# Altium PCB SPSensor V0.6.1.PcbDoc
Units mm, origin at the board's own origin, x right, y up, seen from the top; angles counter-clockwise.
Board outline 97.48 x 57.45 mm, 2 copper layers (TopLayer, BottomLayer), stack 1.671 mm thick; 106 components, 64 nets, 349 pads, 163 vias.
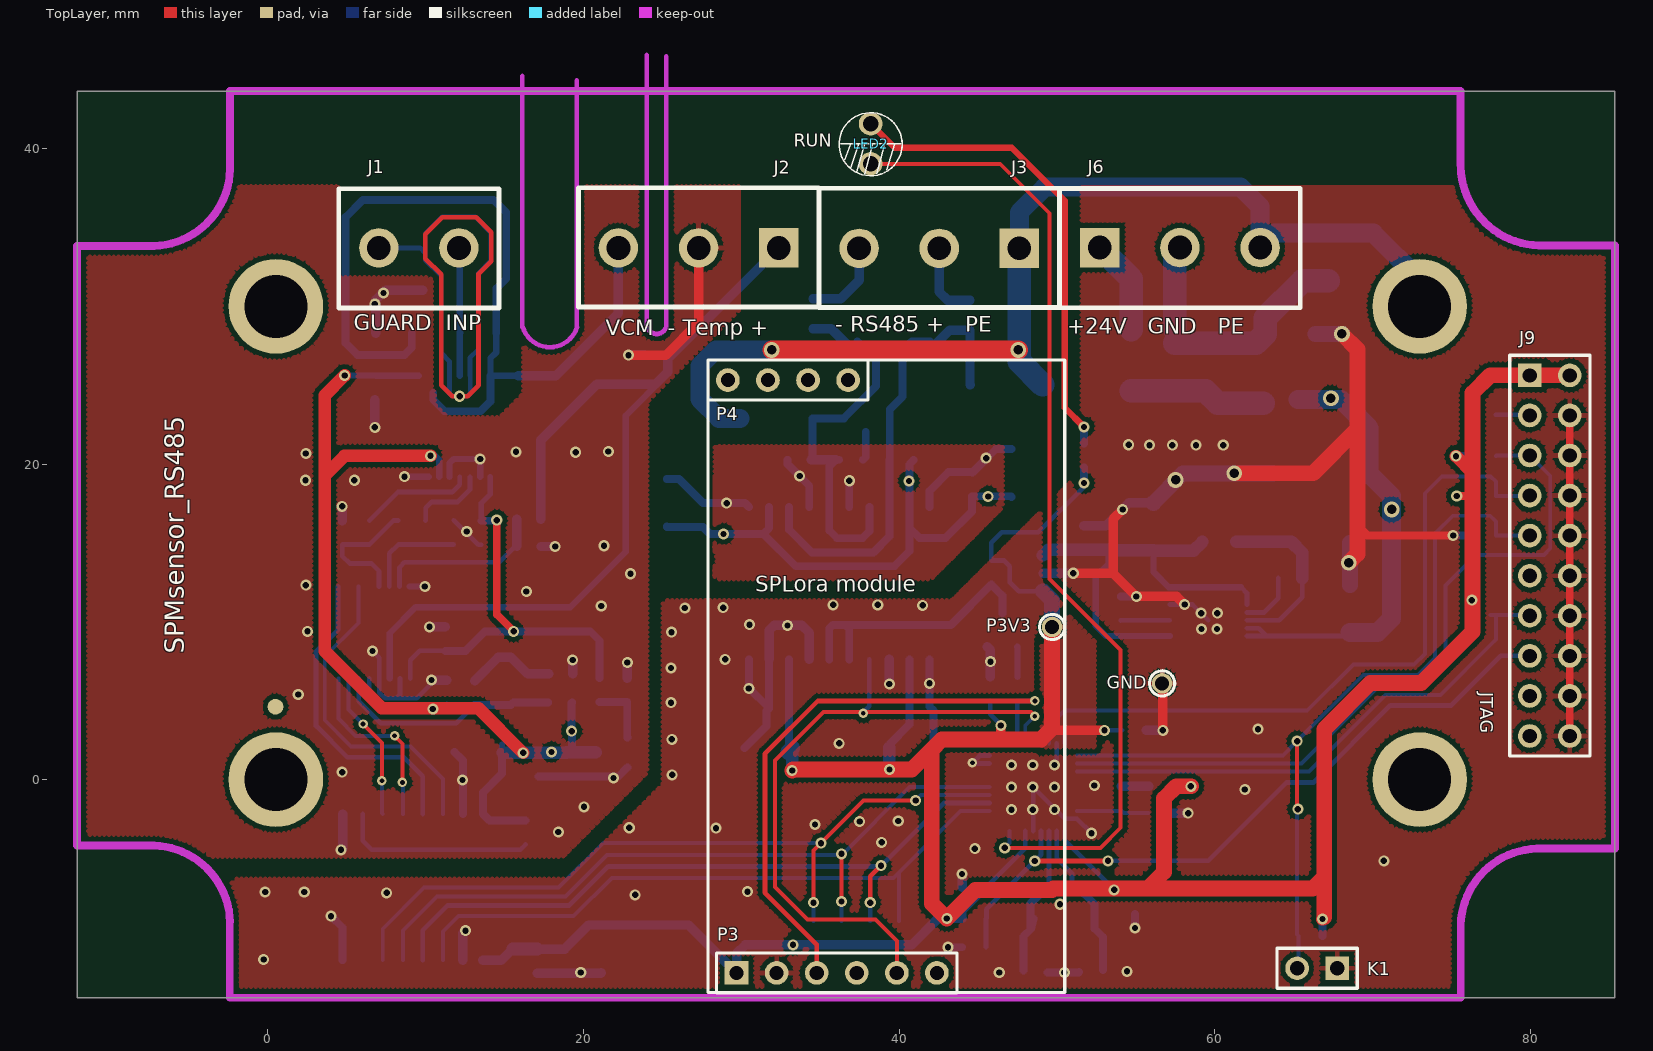
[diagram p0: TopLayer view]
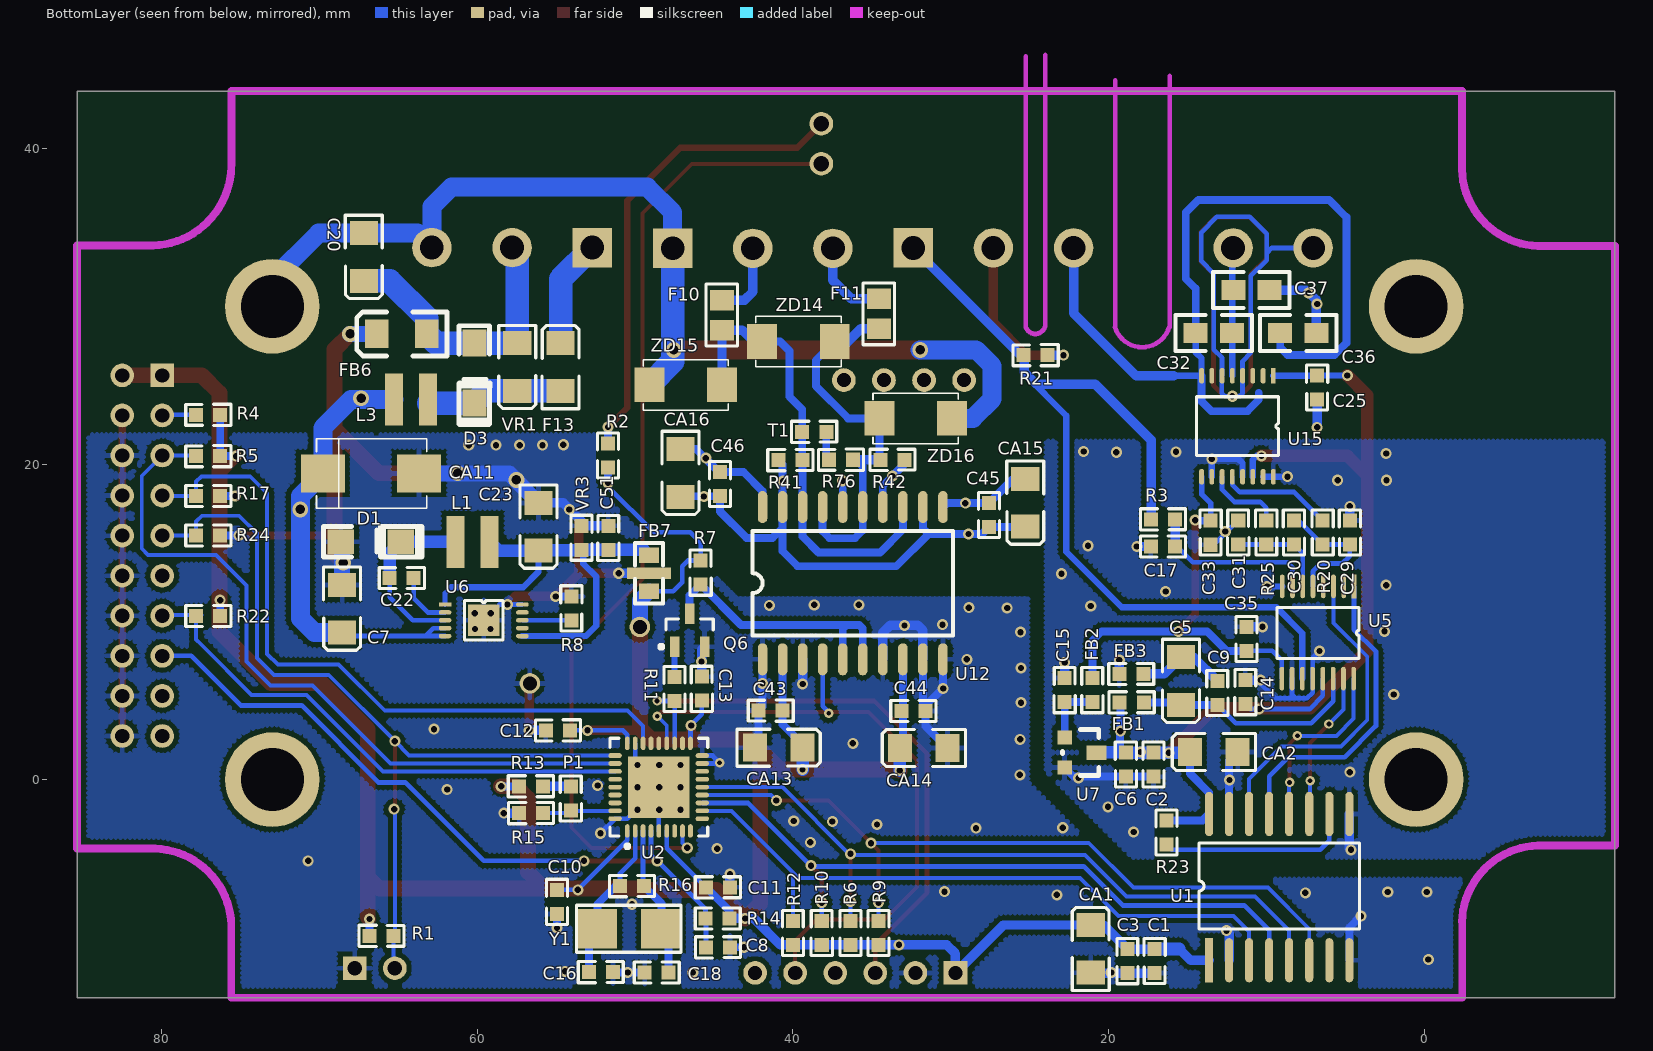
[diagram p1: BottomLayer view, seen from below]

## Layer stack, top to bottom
TopLayer: signal copper 0.0356
Dielectric: core 1.6, FR-4, Dk 4.8
BottomLayer: signal copper 0.0356

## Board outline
-12.1,-13.825 85.375,-13.825 85.375,43.625 -12.1,43.625

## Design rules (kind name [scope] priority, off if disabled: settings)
Clearance Clearance_poly [InPolygon] p1: gap=0.3
Clearance [All] p2: gap=0.15
ComponentClearance [All] p1: gap=0.15 collisioncheckmode=3 verticalgap=0.254 showdistances=FALSE
FabricationTestPointUsage TestPointUsage [All] p1: valid=0 allowmultiple=FALSE
FabricationTestpoint Testpoint [All] p1: side=3 testpointundercomponent=TRUE minsize=1.016 maxsize=2.54 preferedsize=1.524 minholesize=0.508 maxholesize=1.016 preferedholesize=0.813 testpointgrid=0.025 allowsidetop=TRUE allowsidebottom=TRUE usegrid=TRUE gridtolerance=0
HoleSize [All] p1: absolutevalues=TRUE maxlimit=10 minlimit=0.025 maxpercent=80.000 minpercent=20.000
MinimumSolderMaskSliver [All] p1: minsoldermaskwidth=0.15
PlaneClearance [All] p1: clearance=0.2
PlaneConnect [All] p1: planeconnectstyle=Relief reliefexpansion=0.3 reliefentries=4 reliefconductorwidth=0.3 reliefairgap=0.3
PolygonConnect PolygonConnect_via [IsVia] p1: connectstyle=Direct reliefconductorwidth=0.254 reliefentries=4 polygonreliefangle="90 Angle"
PolygonConnect [All] p2: connectstyle=Relief reliefconductorwidth=0.3 reliefentries=4 polygonreliefangle="90 Angle"
RoutingVias [All] p1: holewidth=0.305 width=0.61 viastyle="Through Hole" minholewidth=0.254 minwidth=0.508 maxholewidth=2 maxwidth=5
SilkToSilkClearance [All] p1: silktosilkclearance=0
SilkscreenOverComponentPads [All] p1: minsilkscreentomaskgap=0
SolderMaskExpansion [All] p1: expansion=0.102
Width [All] p1: maxlimit=5.08 minlimit=0.1 preferedwidth=0.254
19 further rules are at their usual default settings.

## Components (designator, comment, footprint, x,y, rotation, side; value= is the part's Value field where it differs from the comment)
C1 "10nF" SM0603 17.025,-11.5 r270 bottom
C2 "0.1uF" SM0603 17.1,0.95 r270 bottom
C3 "0.1uF" SM0603 18.85,-11.5 r90 bottom
C5 "10uF" SM1206 15.4,6.25 r270 bottom
C6 "4.7uF" SM0603 18.85,0.95 r270 bottom
C7 "4.7uF/50V" SM1206 68.575,10.825 r270 bottom
C8 "0.1uF" SM0603 44.75,-10.575 r180 bottom
C9 "0.1uF" SM0603 13.15,5.5 r90 bottom
C10 "0.1uF" SM0603 54.905,-7.75 r270 bottom
C11 "0.1uF" SM0603 44.755,-6.775 r180 bottom
C12 "0.1uF" SM0603 54.9,3.075 r0 bottom
C13 "0.1uF" SM0603 45.83,5.765 r90 bottom
C14 "0.1uF" SM0603 11.375,5.55 r90 bottom
C15 "1uF" SM0603 22.825,5.675 r90 bottom
C16 "22pF" SM0603 52.175,-12.15 r180 bottom
C17 "1uF" SM0603 16.555,14.725 r0 bottom
C18 "22pF" SM0603 48.64,-12.275 r0 bottom
C20 "1nF/2kV" SM1206 67.2,33.125 r270 bottom
C22 "0.47uF" SM0603 64.8,12.725 r0 bottom
C23 "22uF" SM1206 56.125,16.025 r270 bottom
C25 "0.1uF" SM0603 6.725,24.85 r270 bottom
C29 "1uF" SM0603 4.65,15.66 r270 bottom
C30 "100pF" SM0603 8.2,15.66 r270 bottom
C31 "1uF" SM0603 11.825,15.675 r90 bottom
C32 "1nF/2kV" 0805 12.175,28.325 r0 bottom (schematic designator C4)
C33 "0.1uF" SM0603 13.475,15.65 r270 bottom
C35 "0.1uF" SM0603 11.3,8.925 r90 bottom
C36 "1nF" 0805 9.125,28.3 r180 bottom (schematic designator C21)
C37 "1nF" 0805 12.1,31.025 r180 bottom (schematic designator C19)
C43 "0.1uF" SM0603 41.415,4.325 r0 bottom
C44 "0.1uF" SM0603 32.36,4.4 r180 bottom
C45 "0.1uF" SM0603 27.625,16.775 r90 bottom
C46 "0.1uF" SM0603 44.575,18.725 r270 bottom
C51 "0.1uF" SM0603 51.75,15.325 r90 bottom
CA1 "10uF" SM1206 21.125,-10.725 r90 bottom
CA2 "10uF" SM1206 13.325,1.75 r0 bottom
CA11 "47uF/50V" D 69.8,19.4 r180 bottom
CA13 "10uF" SM1206 40.9,2.025 r180 bottom
CA14 "10uF" SM1206 31.715,2 r0 bottom
CA15 "10uF" SM1206 25.275,17.55 r270 bottom
CA16 "10uF" SM1206 47.125,19.435 r270 bottom
D1 "CD1607-B140" 1206D 68.467,15.075 r180 bottom
D3 "1N4007" 1206D 60.2,27.475 r270 bottom
F10 "FUSE1" SM0805 44.475,29.425 r90 bottom
F11 "FUSE1" SM0805 34.525,29.5 r90 bottom
F13 "1A" SM1206 54.725,26.15 r90 bottom
FB1 "BLM18PG600SN1" SM0603 18.525,4.95 r180 bottom
FB2 "BLM18PG600SN1" SM0603 21.075,5.675 r90 bottom
FB3 "BLM18PG600SN1" SM0603 18.55,6.75 r180 bottom
FB6 "BLM31PG500SN1" 1206 66.25,28.25 r0 bottom
FB7 "NFM21PC105B1C3" NFM21PC105 49.125,14.225 r270 bottom
GND "TestPoint" "test point" 56.675,6.1 r90 top
J1 "PH2-5.08mm" PH2-5.08mm 7.025,33.7 r0 top
J2 "PH3-5.08mm" PH3-5.08mm 32.375,33.7 r180 top
J3 "PH3-5.08mm" PH3-5.08mm 47.625,33.675 r180 top
J6 "PH3-5.08mm" PH3-5.08mm 52.725,33.725 r0 top
J9 "JTAG" HDR2X10 79.975,25.625 r270 top
K1 "KEY1" HDR1x2 67.775,-11.955 r180 top (schematic designator R1)
L1 "LPS3010-472ML" LPS3010 61.385,15.075 r180 bottom
L3 "LPS3010-472ML" LPS3010 63.125,24.1 r0 bottom
LED2 "RUN" LED 38.2,41.575 r270 top
P1 "NC" sm0603 54.13,-1.185 r90 bottom
P3 "Header 6" HDR1X6 29.7,-12.25 r0 top
P3V3 "TestPoint" "test point" 49.7,9.675 r90 top
P4 "Lora module" HDR1X4 29.15,25.325 r0 top
Q6 "MMBT3904" SOT23_N 46.55,9.475 r90 bottom
R1 "10K" SM0603 66.075,-9.855 r180 bottom
R2 "560R" SM0603 51.775,20.55 r90 bottom
R3 "10K" SM0603 16.54,16.55 r180 bottom
R4 "10K" SM0603 77.065,23.075 r0 bottom
R5 "10K" SM0603 77.065,20.45 r0 bottom
R6 "100K" SM0603 36.401,-9.713 r90 bottom
R7 "4.7K" SM0603 45.9,13.125 r90 bottom
R8 "49.9K" SM0603 54,10.85 r270 bottom
R9 "100K" SM0603 34.626,-9.713 r90 bottom
R10 "100K" SM0603 38.226,-9.713 r90 bottom
R11 "1K" SM0603 47.555,5.75 r90 bottom
R12 "100K" SM0603 40.051,-9.713 r90 bottom
R13 "1K" SM0603 56.605,-0.375 r180 bottom
R14 "10K" SM0603 44.775,-8.85 r0 bottom
R15 "100K" SM0603 56.59,-2.075 r180 bottom
R16 "10M" SM0603 50.2,-6.7 r180 bottom
R17 "10K" SM0603 77.065,17.925 r0 bottom
R20 "10K" SM0603 6.375,15.66 r270 bottom
R21 "NC" SM0603 24.625,26.85 r0 bottom
R22 "10K" SM0603 77.065,10.325 r0 bottom
R23 "4.7K" SM0603 16.375,-3.35 r90 bottom
R24 "NC" SM0603 77.065,15.425 r0 bottom
R25 "10K" SM0603 9.95,15.66 r270 bottom
R41 "47K" SM0603 40.16,20.3 r180 bottom
R42 "47K" SM0603 33.685,20.325 r180 bottom
R76 "120R" SM0603 36.965,20.225 r0 bottom
T1 "" SM0603 38.65,22.1 r180 bottom
U1 "ADuM5401ARWZ" ADUM1401 13.625,-11.45 r90 bottom locked
U2 "STM32F103TBU6" VFQN36_V 48.5,-0.475 r90 bottom locked
U5 "AD7793BRU" AD7793 6.725,9.325 r270 bottom
U6 "LT3971IMSE-3.3" LT3971 59.6,10.1 r270 bottom
U7 "AD1584BRTZ" SOT-23 20.63,0.339 r270 bottom
U12 "ADM2587E" SOL-20 41.925,7.625 r90 bottom
U15 "LMP91200" LMP91200 11.825,22.4 r0 bottom
VR1 "V42MLA1206N" SM1206 57.475,26.15 r270 bottom
VR3 "V3.5MLA0603N" SM0603 53.35,15.325 r270 bottom (schematic designator VA2)
Y1 "8MHz" CY5.4X4.6 52.375,-9.45 r180 bottom
ZD14 "SMBJ12" ZD 41.95,27.775 r180 bottom
ZD15 "SMBJ12" ZD 44.5,25.025 r0 bottom
ZD16 "SMBJ12" ZD 29.925,22.9 r0 bottom

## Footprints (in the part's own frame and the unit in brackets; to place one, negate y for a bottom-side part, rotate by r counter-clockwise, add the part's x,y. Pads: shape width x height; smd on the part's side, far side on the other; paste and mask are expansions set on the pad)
0805 [mil]
  rect 60x50 smd: 1(0.39,0.31) 2(90.39,0.31)
  silkscreen extent -50,-45 140,45
1206 [mm]
  rect 1.5x1.8 smd: 1(-3.048,0) 2(0.127,0)
  silkscreen extent -4.32,-1.4 1.4,1.4
1206D [mm]
  rect 1.7x1.524 smd: 1(-0.19,0.003) 2(3.61,0.003)
  silkscreen extent -1.3,-0.97 4.96,0.99
AD7793 [mm]
  rect 1.5x0.3 smd: 1(-2.921,2.286)
  oval 1.5x0.3 smd: 2(-2.921,1.636) 3(-2.921,0.986) 4(-2.921,0.336) 5(-2.921,-0.314) 6(-2.921,-0.964) 7(-2.921,-1.614) 8(-2.921,-2.264) 9(2.921,-2.286) 10(2.921,-1.636) 11(2.921,-0.986) 12(2.921,-0.336) 13(2.921,0.314) 14(2.921,0.964) 15(2.921,1.614) 16(2.921,2.264)
  silkscreen extent -1.59,-2.59 1.64,2.61
ADUM1401 [mm]
  rect 2.8x0.51 smd: 1(0,0)
  oval 2.8x0.51 smd: 2(0,-1.27) 3(0,-2.54) 4(0,-3.81) 5(0,-5.08) 6(0,-6.35) 7(0,-7.62) 8(0,-8.89) 9(9.271,-8.89) 10(9.271,-7.62) 11(9.271,-6.35) 12(9.271,-5.08) 13(9.271,-3.81) 14(9.271,-2.54) 15(9.271,-1.27) 16(9.271,0)
  silkscreen extent 1.99,-9.53 7.43,0.63
CY5.4X4.6 [mm]
  rect 2.5x2.5 smd: 1(-0.025,0) 2(4,0)
  silkscreen extent -1.35,-1.49 5.28,1.49
D [mil]
  rect 110x94.49 smd: 1(0,0) 2(240,0)
  silkscreen extent -16,-87 260,87
HDR1x2 [mm] "Connector; Header; 2 Position"
  rect 1.5x1.5 hole 0.9: 1(0,0)
  round 1.5 hole 0.9: 2(2.54,0)
  silkscreen extent -1.27,-1.27 3.81,1.27
HDR1X4 [mm] "Connector; Header; 4 Position"
  round 1.5 hole 0.9: 1(0,0) 2(2.54,0) 3(5.08,0) 4(7.62,0)
  silkscreen extent -1.27,-1.27 8.89,1.27
HDR1X6 [mm] "Connector; Header; 6 Position"
  rect 1.5x1.5 hole 0.9: 1(0,0)
  round 1.5 hole 0.9: 2(2.54,0) 3(5.08,0) 4(7.62,0) 5(10.16,0) 6(12.7,0)
  silkscreen extent -1.27,-1.27 13.97,1.27
HDR2X10 [mm] "Connector; Header; 10x2 Position"
  rect 1.5x1.5 hole 0.9: 1(0,0)
  round 1.5 hole 0.9: 2(0,2.54) 3(2.54,0) 4(2.54,2.54) 5(5.08,0) 6(5.08,2.54) 7(7.62,0) 8(7.62,2.54) 9(10.16,0) 10(10.16,2.54) 11(12.7,0) 12(12.7,2.54) 13(15.24,0) 14(15.24,2.54) 15(17.78,0) 16(17.78,2.54) 17(20.32,0) 18(20.32,2.54) 19(22.86,0) 20(22.86,2.54)
  silkscreen extent -1.27,-1.27 24.13,3.81
LED [mm]
  round 1.5 hole 1: 1(0,0) 2(2.54,0)
  silkscreen extent -0.7,-2 3.3,2
LMP91200 [mm]
  rect 0.3x1 smd: 1(-2.275,-3.2)
  oval 0.3x1 smd: 2(-1.625,-3.2) 3(-0.975,-3.2) 4(-0.325,-3.2) 5(0.325,-3.2) 6(0.975,-3.2) 7(1.625,-3.2) 8(2.275,-3.2) 9(2.275,3.2) 10(1.625,3.2) 11(0.975,3.2) 12(0.325,3.2) 13(-0.325,3.2) 14(-0.975,3.2) 15(-1.625,3.2) 16(-2.275,3.2)
  silkscreen extent -2.6,-1.87 2.6,1.87
LPS3010 [mm]
  rect 1.14x3.3 smd: 1(0,0) 2(2.16,0)
LT3971 [mm]
  rect 0.28x0.8 smd: 1(-1,-2.45)
  oval 0.28x0.8 smd: 2(-0.5,-2.45) 3(0,-2.45) 4(0.5,-2.45) 5(1,-2.45) 6(1,2.45) 7(0.5,2.45) 8(0,2.45) 9(-0.5,2.45) 10(-1,2.45)
  rect 2x2 smd: 11(0,0)
  silkscreen extent -1.25,-1.21 1.25,1.22
NFM21PC105 [mm]
  rect 1x1.27 smd: 1(0.01,0.008) 2(2.286,0)
  rect 0.7x2.8 smd: 3(1.143,0)
  silkscreen extent -0.76,-0.89 3.05,0.89
PH2-5.08mm [mm]
  round 2.5 hole 1.5: 1(0,0) 2(5.08,0)
  silkscreen extent -2.54,-3.81 7.62,3.75
PH3-5.08mm [mm]
  rect 2.5x2.5 hole 1.5: 1(0,0)
  round 2.5 hole 1.5: 2(5.08,0) 3(10.16,0)
  silkscreen extent -2.54,-3.81 12.7,3.75
SM0603 [mil]
  rect 35x35 smd: 1(-30,-2) 2(30,-2)
  silkscreen extent -57,-28 56,24
sm0603 [mil]
  rect 35x35 smd: 1(-30,-2) 2(30,-2)
  silkscreen extent -57,-28 56,24
SM0805 [mm]
  rect 1.3x1.5 smd: 1(-0.933,0.022) 2(0.967,0.022)
  silkscreen extent -1.93,-0.97 1.98,1.04
SM1206 [mil]
  rect 60x70 smd: 1(59.5,0) 2(-59.5,0)
  silkscreen extent -104,-46 104,46
SOL-20 [mil]
  oval 80x24 smd: 1(0,0) 2(0,-50) 3(0,-100) 4(0,-150) 5(0,-200) 6(0,-250) 7(0,-300) 8(0,-350) 9(0,-400) 10(0,-450) 11(380,-450) 12(380,-400) 13(380,-350) 14(380,-300) 15(380,-250) 16(380,-200) 17(380,-150) 18(380,-100) 19(380,-50) 20(380,0)
  silkscreen extent 60,-475 320,25
SOT23_N [mm] "SOT23, 3-Leads, Body 2.9x1.3mm, Pitch 0.95mm, Lead Span 2.3mm, IPC Medium Density"
  rect 1.3x0.6 smd: 1(-1.05,0.95) 2(-1.05,-0.95) 3(1.05,0)
  silkscreen extent -1.17,-1.5 0.7,1.93, body extent -0.7,-1.5 0.7,1.5, height 1.1
SOT-23 [mil]
  rect 36x36 smd: 1(-91.86,-84.66) 2(-16.86,-84.66)
  rect 36x50 smd: 3(-53.86,-4.66)
  silkscreen extent -112,-90 3,0
"test point" [mm]
  round 1.3 hole 0.9: 1(0,0)
  silkscreen extent -0.8,-0.8 0.8,0.8
VFQN36_V [mm] "QFN, 36-Leads, Body 6x6mm, Pitch 0.5mm, ST Recommended"
  oval 0.85x0.3 smd: 1(-2.775,2) 2(-2.775,1.5) 3(-2.775,1) 4(-2.775,0.5) 5(-2.775,0) 6(-2.775,-0.5) 7(-2.775,-1) 8(-2.775,-1.5) 9(-2.775,-2) 19(2.775,-2) 20(2.775,-1.5) 21(2.775,-1) 22(2.775,-0.5) 23(2.775,0) 24(2.775,0.5) 25(2.775,1) 26(2.775,1.5) 27(2.775,2)
  oval 0.3x0.85 smd: 10(-2,-2.755) 11(-1.5,-2.755) 12(-1,-2.755) 13(-0.5,-2.755) 14(0,-2.755) 15(0.5,-2.755) 16(1,-2.755) 17(1.5,-2.755) 18(2,-2.755) 28(2,2.775) 29(1.5,2.775) 30(1,2.775) 31(0.5,2.775) 32(0,2.775) 33(-0.5,2.775) 34(-1,2.775) 35(-1.5,2.775) 36(-2,2.775)
  rect 3.9x3.9 smd: 37(0,0)
  silkscreen extent -3.87,-3.1 3.1,3.1, body extent -3.05,-3.05 3.05,3.05, height 1
ZD [mm]
  rect 1.9x2.2 smd: 1(0,0) 2(4.6,0)
  silkscreen extent -0.4,-1.6 5,1.6

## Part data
C1 C6 C7 C9 C14 C15 C17 C20 C22 C25 C29 C30 C31 C32 C33 C35 C36 C37 C51: library part CAP, "Capacitor"
C2 C3 C43 C44 C45 C46: library part C, "电?"
C5 CA11 CA13 CA14 CA15 CA16: library part CAPE, "¼«Ð"
C8: library part Cap, "Capacitor, X7R Ceramic"
C10 C11 C12 C13 C16 C18: library part Cap, "Capacitor"
C23: library part C, "¼«Ð"
CA1 CA2: library part CAPE, "Capacitor"
D1: library part DIODE, "Diode"
D3: library part "Diode 1N4007", "1 Amp General Purpose Rectifier"
F10 F11: "Fuse"
F13: library part FUSE1, "Fuse"
FB1 FB3 L1 L3: library part INDUCTOR
FB2 FB6 FB7: library part Inductor, "Inductor"
J1 K1: library part "Header 2", "Header, 2-Pin"
J2 J3 J6: library part CON3, "Connector"
J9: library part "Header 10X2", "Header, 10-Pin, Dual row"
LED2: library part LED0, "Typical INFRARED GaAs LED"
P1: library part H, "Header, 2-Pin, 2.54mm, 排?"
P3: "Header, 6-Pin"
P4: library part "Header 4", "Header, 4-Pin"
Q6: "NPN Switching Transistor"
R1 R2 R7 R11 R16: library part Res2, "Resistor"
R3 R4 R5 R6 R9 R10 R12 R17 R20 R21 R22 R24 R25: library part RE, "电?"
R8 R13 R14 R15 R23 R41 R42 R76: library part R, "电?"
T1: library part CON2, "Connector"
U1: library part ADUM1401, "1Mbps Data Rate, 100ns Propagation delay"
U2: library part STM32F103T8U6, "STM32 ARM-based 32-bit MCU with 64 Kbytes Flash, 36-pin VFQFPN, Industrial Temperature"
U5: library part AD7793
U6: library part LT3971
U7: library part "Header 3", "4.096V reference"
VR1: library part "Res Varistor", "Varistor (Voltage-Sensitive Resistor)"
VR3: library part "D Zener", "Zener Diode"
Y1: library part XTAL, "Crystal Oscillator"
ZD14 ZD15 ZD16: library part SMBJ, "瞬变"

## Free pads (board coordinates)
  round 1 smd: 0(0.475,4.625)
  round 6 hole 4: 3(73,30) 4(73,0) 5(0.5,0) 6(0.5,30)

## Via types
v1: diameter 0.7, hole 0.4, TopLayer to BottomLayer, 147 vias
v2: diameter 0.6, hole 0.3, TopLayer to BottomLayer, 8 vias
v3: diameter 1, hole 0.6, TopLayer to BottomLayer, 8 vias

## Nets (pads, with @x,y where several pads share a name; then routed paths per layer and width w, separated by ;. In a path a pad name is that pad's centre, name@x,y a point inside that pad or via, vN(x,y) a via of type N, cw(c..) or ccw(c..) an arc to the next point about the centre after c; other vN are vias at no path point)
24VGND_IN: C20.1 D3.1 FB6.1 J6.2 VR1.2 | length 17.8
  BottomLayer w1.5: VR1.2 60.193,27.661 D3.1 62.617,27.665 FB6.1 63.202,29.252 65.564,31.614 C20.1 ; 57.475,28.536 57.475,33.395 J6.2 J6.2@58.147,33.383
+24V: C7.1 CA11.1 L3.2 U6.4 U6.5 | length 29
  BottomLayer w0.3: U6.5 63.3,9.1 ; U6.4 62.8,9.6 63.3,9.1 ; C7.1 68.361,9.1 63.3,9.1
  BottomLayer w1.2: L3.2 68,24.1 69.8,22.3 CA11.1 71.225,17.975 71.225,10.225 70.314,9.314 C7.1
  other v3: 71.225,17.125 67.375,24.175
+24V_IN: F13.1 J6.1 | length 6.1
  BottomLayer w1.5: J6.1@52.675,33.675 J6.1 54.725,31.725 54.725,28.536
BOOT0: P1.1 R15.2 U2.35 | length 4.6
  BottomLayer w0.25: U2.35 54.052,-1.975 P1.1 54.258,-2.126 R15.2
DE485: Q6.3 R7.1 U12.5 U12.6 | length 17.8
  BottomLayer w0.5: U12.6 35.575,9.575 35.8,9.8 36.6,9.8 ; U12.5 36.845,9.555 36.6,9.8 ; Q6.3 46.55,11.662 R7.1 43.286,9.8 36.6,9.8
DVDD: C5.1 C9.1 FB1.2 U5.14 | length 14.6
  BottomLayer w0.3: U5.14 5.761,4.964 7.15,3.575 11.936,3.575 C9.1
  BottomLayer w0.5: C9.1 C5.1 15.561,4.899 FB1.2
EARTH: C20.2 J3.1 J6.3 pad.3 ZD15.2 ZD16.1 | length 69.8
  TopLayer w1.2: v3(31.938,27.237) v3(47.562,27.237)
  BottomLayer w1.2: ZD16.1 28.6,22.9 27.375,24.125 27.375,26.225 28.387,27.237 v3(31.938,27.237) ; J3.1 47.625,35.95 49.225,37.55 61.65,37.55 62.885,36.315 J6.3 63.796,34.636 C20.2 70.064,34.636 73,31.7 pad.3
  BottomLayer w1.5: J3.1@47.675,33.625 J3.1 47.625,26.5 ZD15.2
GND: C1.2 C3.1 C7.2 C8.2 C10.2 C11.2 C12.2 C13.2 C16.2 C18.2 C23.2 C43.2 C44.2 C51.2 CA1.2 CA11.2 CA13.2 CA14.2 D1.1 FB6.2 FB7.3 GND.1 J9.4 J9.6 J9.8 J9.10 J9.12 J9.14 J9.16 J9.18 J9.20 K1.1 P3.2 Q6.2 R8.1 R15.1 R24.1 U1.2 U1.8 U2.5 U2.17 U2.18 U2.26 U2.36 U2.37 U6.10 U6.11 U12.1 U12.3 U12.7 U12.9 U12.10 VR3.1 | length 143.3
  TopLayer w0.3: v1@52.35,-0.375 v1(52.375,-0.375)
  TopLayer w0.5: 69.05,16.125 69.699,15.476 v1(75.125,15.476) ; J9.20 J9.18 J9.16 J9.14 J9.12 J9.10 J9.8 J9.6 J9.4
  TopLayer w0.6: v1(51.043,13.082) 53.568,13.082 ; v1(54.175,17.125) 53.568,16.518 53.568,13.082 ; GND.1 56.724,6.051 v1(56.724,3.126) ; v1(58.1,11.1) 57.588,11.612 v1(55.038,11.612) 53.568,13.082
  TopLayer w1: v3(61.25,19.425) 66.25,19.425 69.05,22.225 ; v3(68.075,28.25) 69.05,27.275 69.05,22.225 ; v3(68.5,13.75) 69.05,14.3 69.05,16.125 69.05,22.225
  BottomLayer w0.3: U2.17 44.7,1.025 v2(44.65,1.075) 45.1,1.525 U2.18 ; U2.5 U2.37 50.5,-2.475 U2.36 v1(52.2,-3.4) ; U2.37@50,1.025 U2.26 ; U6.10 58.6,11.1 U6.11
  BottomLayer w0.5: v1(4,-8.65) 4.735,-9.385 U1.8 ; CA14.2 31.598,3.395 C44.2 C44.2@31.765,4.516 ; U12.10 30.495,5.786 C44.2@31.765,4.516 ; U12.9 C44.2@31.765,4.516 ; U12.1 41.925,4.627 C43.2 CA13.2@42.177,2.059 ; v1(43.101,-10.626) C8.2 ; C18.2 v1(50.475,-12.224) 51.39,-12.224 C16.2 ; R8.1 v1(55.038,11.612) ; v1(54.956,-9.406) C10.2 ; v1(75.125,15.476) R24.1
  BottomLayer w0.6: U1.2 12.355,-9.745 v1(12.525,-9.575) ; C1.2 21.099,-12.262 CA1.2 ; U12.9 31.765,9.465 32.1,9.8 33.825,9.8 34.305,9.32 U12.7 ; v1(39.385,6.06) U12.3 ; C11.2 v1(43.993,-5.982) ; Q6.2 45.779,8.246 C13.2 ; FB7.3 v1(51.043,13.082) ; C51.2 53.112,16.087 54.561,17.536 C23.2 ; C12.2 v1(56.724,3.126) ; R15.1 v1(58.326,-2.126)
  BottomLayer w1: C23.2 57.989,19.4 CA11.2 ; FB6.2 v3(68.075,28.25) ; C7.2 D1.1@68.575,14.995
  other v1: 19.825,-12.225 46.35,-12.225 54.45,-12.15 -0.275,-11.4 50.2,-7.9 23.275,-7.3 7.525,-7.175 -0.181,-7.125 2.3,-7.125 30.4,-7.1 70.725,-5.15 44.8,-4.375 38.9,-3.975 28.4,-3.075 22.9,-3.05 34.675,-2.85 37.5,-2.65 39.95,-2.625 47.125,-1.9 48.475,-1.9 49.85,-1.9 61.919,-0.625 47.125,-0.475 48.475,-0.475 49.85,-0.475 25.619,0.3 47.125,0.925 48.475,0.925 49.85,0.925 36.2,2.3 25.6,2.55 62.75,3.2 25.55,4.875 30.475,5.775 41.925,6.1 25.55,7.075 45.8,7.475 28.975,7.625 25.575,9.35 59.175,9.55 60.15,9.55 32.925,9.775 30.525,9.825 59.15,10.55 60.175,10.55 26.425,10.875 28.85,10.9 41.5,11.05 35.825,11.075 38.65,11.075 55.875,21.2 57.325,21.2 58.825,21.2 60.55,21.2 54.55,21.225
  other v3: 57.525,19
GND_COM: C45.2 C46.1 CA15.2 CA16.2 R42.2 U12.11 U12.14 U12.16 U12.20 | length 18.5
  BottomLayer w0.5: CA15.2 26.05,19.061 C45.2 30.235,17.537 U12.11 ; R42.2 32.923,20.002 34.305,18.62 U12.14 ; U12.16 v1(36.845,18.945) ; U12.20 41.925,18.287 43.125,19.487 C46.1 ; C46.1@44.651,19.462 46.135,20.947 CA16.2
  other v1: 29.075,17.525 33.7,19.25 45.525,20.375
GND_ISO: C2.2 C6.2 C14.2 C15.2 C17.2 C25.2 C29.1 C31.2 C33.2 C35.2 C36.2 C37.2 CA2.2 FB3.1 J2.2 R21.1 U1.9 U1.15 U5.8 U5.10 U5.12 U7.2 U15.10 U15.13 U15.15 U15.16 | length 53.3
  TopLayer w0.6: v1(22.849,26.901) 25.226,26.901 27.295,28.97 J2.2
  BottomLayer w0.3: v1(6.625,8.15) 7.061,7.714 U5.12 7.061,5.514 7.425,5.15 8.125,5.15 ; U5.10 8.361,5.386 8.125,5.15 ; v1(10.362,6.312) 10.362,6.087 9.425,5.15 8.125,5.15 ; C31.2 13.323,14.888 C33.2
  BottomLayer w0.4: v1(8.65,19.2) U15.16 U15.15 ; U5.8 v1(9.946,12.246) ; U15.13 11.5,20.05 11.775,20.325 v1(13.45,20.325) U15.10
  BottomLayer w0.5: CA2.2 12.355,1.209 U1.15 ; C2.2 C6.2 22.202,0.188 U7.2
  BottomLayer w0.6: v1(4.625,-4.45) 4.735,-4.34 U1.9 ; C29.1 v1(4.701,17.324) ; v1(6.776,22.326) C25.2 ; C36.2 6.829,30.404 7.458,31.033 C37.2 ; v1(10.237,9.687) C35.2 ; v1(10.362,6.312) C14.2 ; C17.2 v1(18.201,14.776) ; FB3.1 v1(19.312,7.587) ; C15.2 v1(22.774,7.424) ; v1(22.849,26.901) R21.1
  other v1: 18.4,-3.325 20.025,-1.725 12.325,-0.025 21.9,0.1 4.7,0.475 1.919,5.4 2.5,9.4 21.125,11 16.375,11.925 2.4,12.325 22.975,13.05 21.3,14.825 12.6,15.725 2.375,18.975 5.475,18.975 2.4,20.675 19.5,20.75 15.719,20.775 21.575,20.8 6.775,30.15 7.325,30.85
GUARD: J1.1 U15.4 U15.6 | length 59
  TopLayer w0.3: 9.975,33.025 9.975,34.575 11.05,35.65 13.2,35.65 14.15,34.7 14.15,32.85 13.35,32.05 13.35,25 12.65,24.3 v1(12.15,24.3) 11.675,24.3 10.975,25 10.975,32.025 9.975,33.025
  BottomLayer w0.3: J1.1 9.65,33.7 9.975,33.375 ; U15.6 12.8,26.725 13.325,27.25 13.325,32.075 14.125,32.875 14.125,34.675 13.125,35.675 11.05,35.675 9.975,34.6 9.975,33.375 ; U15.6@12.825,25.6 12.825,24.5 12.625,24.3 v1(12.15,24.3) 11.7,24.3 11.5,24.5 U15.4 11.5,26.525 10.975,27.05 10.975,31.925 9.975,32.925 9.975,33.375
JNTRST: J9.3 R4.2 | length 2.2
  BottomLayer w0.3: R4.2 79.934,23.126 J9.3
JTCK: J9.9 K1.2 R1.2 R24.2 U2.28 | length 55.1
  TopLayer w0.25: v1(65.235,2.435) 65.235,-1.835 v1(65.275,-1.875)
  BottomLayer w0.25: U2.28 64.325,1.525 v1(65.235,2.435) 69.425,6.625 72.9,6.625 73.975,7.7 73.975,15.6 75.1,16.725 77.45,16.725 77.827,16.348 R24.2 77.838,15.465 J9.9 ; K1.2 65.313,-11.877 R1.2 65.235,-9.828 v1@65.235,-1.875
JTDI: J9.5 R5.2 U2.29 | length 47.1
  BottomLayer w0.25: U2.29 65.5,1.025 70.45,5.975 73.125,5.975 74.625,7.475 74.625,12.3 76.575,14.25 80.875,14.25 81.275,14.65 81.275,19.245 J9.5 77.871,20.545 R5.2
JTDO: J9.13 R22.2 U2.30 | length 34
  BottomLayer w0.25: U2.30 65.975,0.525 70.825,5.375 74.327,5.375 77.502,8.55 77.827,8.875 R22.2 ; R22.2@77.502,10.426 79.934,10.426 J9.13
JTMS: J9.7 R17.2 U2.25 | length 45.2
  BottomLayer w0.25: U2.25 49.5,3.4 50.475,4.375 65.875,4.375 68.8,7.3 72.65,7.3 73.325,7.975 73.325,18.15 74.4,19.225 77.5,19.225 77.827,18.898 R17.2 79.946,17.976 J9.7
JTRST: U2.31
KEY1: U2.24
LED_S1: U2.23
LED_S2: LED2.2 U2.8 | length 62.5
  TopLayer w0.25: LED2.2 46.415,39.035 49.55,35.9 49.55,12.725 54.05,8.225 54.05,-3.05 52.775,-4.325 v1(46.7,-4.325)
  BottomLayer w0.25: v1(46.7,-4.325) 47,-4.025 U2.8
LORA_AUX: P3.6
MCU_RXD1: P3.5 U2.22 U12.4 | length 42.7
  TopLayer w0.25: v2(37.725,4.2) v2@37.8,4.275 ; P3.5 39.86,-10.235 38.5,-8.875 34.2,-8.875 32.125,-6.8 32.125,1.2 35.2,4.275 v2@37.8,4.275 ; v2(48.6,4.025) 48.35,4.275 v2@37.8,4.275
  BottomLayer w0.25: U2.22 48,3.425 v2(48.6,4.025)
  BottomLayer w0.3: v2@37.688,4.237 38.115,4.665 U12.4
MCU_TXD1: P3.3 R11.1 U2.21 | length 37.5
  TopLayer w0.3: P3.3 34.78,-10.455 31.5,-7.175 31.5,1.625 34.863,4.988 v2(48.613,4.988)
  BottomLayer w0.3: U2.21 R11.1@47.5,4.983 ; R11.1 v2(48.613,4.988)
MISO1: R9.2 U1.6 U2.13 | length 49.1
  TopLayer w0.25: v1(34.575,-7.8) 34.575,-4.5 v1(35.05,-4.025) 37.75,-1.325 v1(41.05,-1.325)
  BottomLayer w0.25: U1.6 7.275,-9.475 9.9,-6.85 18.425,-6.85 21.25,-4.025 v1(35.05,-4.025) ; R9.2 v1(34.575,-7.8) ; v1(41.05,-1.325) 41.4,-0.975 U2.13
MOSI1: R6.2 U1.5 U2.14 | length 47.1
  TopLayer w0.25: v1(36.35,-7.725) v1(36.35,-4.7)
  BottomLayer w0.25: U1.5 8.545,-9.555 10.7,-7.4 18.85,-7.4 21.475,-4.775 36.375,-4.775 40.675,-0.475 U2.14 ; R6.2 v1(36.35,-7.725)
NetC5_2: C5.2 C9.2 FB3.2 | length 5.7
  BottomLayer w0.6: C9.2 14.599,7.761 C5.2 16.462,6.699 FB3.2
NetC15_1: C15.1 FB2.1 U7.1 | length 4
  BottomLayer w0.5: FB2.1 C15.1 22.774,2.678 U7.1
NetC16_1: C16.1 R16.1 U2.2 Y1.1 | length 9.9
  BottomLayer w0.3: U2.2 50,-4.97 50.962,-5.932 R16.1
  BottomLayer w0.5: R16.1@51.251,-6.751 52.4,-7.9 Y1.1 52.937,-9.987 C16.1@52.937,-12.076
NetC17_1: C17.1 R3.2 U5.7 | length 11
  BottomLayer w0.3: U5.7 8.339,13.464 8.65,13.775 14.65,13.775 C17.1@15.793,14.918
  BottomLayer w0.6: C17.1@15.778,14.79 R3.2
NetC18_1: C18.1 R16.2 U2.3 Y1.2 | length 10.2
  BottomLayer w0.3: R16.2@49.5,-6.689 U2.3
  BottomLayer w0.5: C18.1@47.878,-12.099 47.878,-9.947 Y1.2 Y1.2@48.525,-8.814 ; Y1.2@48.338,-9.413 48.338,-7.851 R16.2@49.5,-6.689
NetC22_1: C22.1 U6.2 | length 3.6
  BottomLayer w0.3: U6.2 63.15,10.6 64.038,11.488 C22.1
NetC22_2: C22.2 D1.2 L1.1 U6.3 | length 11.4
  BottomLayer w0.3: U6.3 64.1,10.1 65.562,11.562 C22.2
  BottomLayer w0.8: L1.1 61.388,15.078 D1.2 65.562,14.373 C22.2
NetC23_1: C23.1 C51.1 FB7.1 L1.2 U6.1 U6.6 VR3.2 | length 28.9
  BottomLayer w0.3: 61.675,12.2 62.05,11.825 U6.1
  BottomLayer w0.4: VR3.2@53.287,14.526 53.287,13.687 52.475,12.875 52.475,9.75 53.125,9.1 U6.6 ; C23.1 56.125,13.175 57.1,12.2 61.675,12.2
  BottomLayer w0.8: FB7.1 49.465,14.563 C51.1 VR3.2 ; VR3.2@53.626,14.538 56.101,14.538 C23.1 58.664,14.514 L1.2
NetC29_2: C29.2 C30.1 R20.2 U5.5 | length 8.6
  BottomLayer w0.3: U5.5 7.039,13.211 6.55,13.7 5.175,13.7 4.701,14.174 C29.2 R20.2 7.95,16.422 C30.1
NetC30_2: C30.2 C31.1 R25.2 U5.6 | length 6.4
  BottomLayer w0.3: U5.6 7.689,14.336 C30.2 R25.2 11.759,14.898 C31.1
NetD3_2: D3.2 F13.2 L3.1 VR1.1 | length 8.7
  BottomLayer w1.5: F13.2 VR1.1 59.424,24.639 D3.2 L3.1@63.09,23.865
NetF10_1: F10.1 R41.2 T1.1 U12.13 U12.18 ZD14.1 ZD15.1 | length 29.6
  BottomLayer w0.5: U12.13 33.035,15.84 34.475,14.4 38.375,14.4 39.385,15.41 U12.18 39.385,20.236 R41.2 39.412,20.263 T1.1 39.412,23.462 40.225,24.275 40.225,27.175 40.825,27.775 ZD14.1
  BottomLayer w0.6: ZD14.1@41.8,27.075 43.217,28.492 F10.1 44.497,25.028 ZD15.1
NetF11_1: F11.1 R42.1 R76.1 U12.15 U12.17 ZD14.2 ZD16.2 | length 25
  BottomLayer w0.5: R42.1 34.525,20.352 ZD16.2 36.5,22.9 38.55,24.95 38.55,26.575 ZD14.2 ; R76.1 36.003,20.276 36.001,20.274 35.575,19.848 U12.15 35.575,15.8 36.075,15.3 37.675,15.3 38.115,15.74 U12.17
  BottomLayer w0.6: R42.1 R76.1@36.001,20.274 ; F11.1 35.708,28.567 ZD14.2@37.2,27.075
NetLED2_1: LED2.1 R2.2 | length 30.2
  TopLayer w0.4: LED2.1 39.725,40.05 47.15,40.05 50.5,36.7 50.5,23.575 v1(51.724,22.351)
  BottomLayer w0.5: R2.2 v1(51.724,22.351)
NetP1_2: P1.2 R13.2 | length 1.8
  BottomLayer w0.6: P1.2 55.841,-0.423 R13.2
NetQ6_1: Q6.1 R11.2 | length 1.9
  BottomLayer w0.4: Q6.1 47.504,8.421 R11.2
NetR8_2: R8.2 U6.8 | length 3.1
  BottomLayer w0.3: R8.2 54.063,10.1 U6.8
NetR20_1: R20.1 U15.12 | length 7.2
  BottomLayer w0.3: R20.1 8.229,18.225 11.675,18.225 12.15,18.7 U15.12
NetR23_1: R23.1 U1.10 | length 12.4
  BottomLayer w0.3: U1.10 6.005,-3.88 6.575,-4.45 15.986,-4.45 R23.1
NetR25_1: R25.1 U15.11 | length 4.9
  BottomLayer w0.3: R25.1@9.975,16.448 R25.1 10.001,17.226 10.375,17.6 12.025,17.6 12.8,18.375 U15.11
NetR76_2: R76.2 T1.2 | length 1.8
  BottomLayer w0.5: R76.2 37.888,20.437 T1.2
PH-INP: C32.1 C37.1 J1.2 U15.5 | length 8.2
  BottomLayer w0.4: J1.2 12.15,33.655 C32.1@12.15,28.282 ; U15.5 C32.1@12.15,28.282 ; C32.1 C32.1@12.15,28.282
PH-VCM: C32.2 C36.1 J2.3 U15.8 | length 55.4
  BottomLayer w0.4: C32.2 14.471,27.075 14.1,26.704 U15.8 15.875,25.6
  BottomLayer w0.5: C36.1 9.115,27.39 8.65,26.925 5.675,26.925 4.925,27.675 4.925,35.65 6.025,36.75 14.3,36.75 15.1,35.95 15.1,31.75 14.471,31.121 C32.2 ; 10.475,24.5 10.475,24.075 11.2,23.35 13.475,23.35 14.1,23.975 U15.8
  BottomLayer w0.6: 15.875,25.6 18.25,25.6 22.215,29.565 J2.3
RS485+: F10.2 J3.2 | length 4.9
  BottomLayer w0.6: J3.2 42.545,30.919 43.072,30.392 F10.2
RS485-: F11.2 J3.3 | length 5.4
  BottomLayer w0.6: F11.2 36.292,30.467 37.465,31.64 J3.3
RST#: C8.1 J9.15 R14.2 U2.4 | length 45.6
  TopLayer w0.3: v1(48.6,-5.155) 53.245,-5.155 v1(53.25,-5.15)
  BottomLayer w0.3: C8.1 45.512,-8.824 R14.2 45.537,-8.218 v1(48.6,-5.155) 49,-4.755 U2.4 ; v1(53.25,-5.15) 59.6,-5.15 64.575,-0.175 66.275,-0.175 71.15,4.7 75,4.7 78.145,7.845 J9.15
RX485: U2.10
SCK1: R10.2 U1.4 U2.12 | length 44.9
  TopLayer w0.3: v1(38.175,-7.8) 38.175,-6.125 v1(38.85,-5.45)
  BottomLayer w0.3: U1.4 9.815,-9.56 11.4,-7.975 19.1,-7.975 21.575,-5.5 38.825,-5.5 42.85,-1.475 U2.12 ; R10.2 v1(38.175,-7.8)
SPI_CS: U1.14 U5.3 | length 20.6
  BottomLayer w0.25: U5.3 5.739,9.939 3.6,7.8 3.6,3.775 5.275,2.1 9.025,2.1 11.085,0.04 U1.14
SPI_DIN: U1.12 U5.16 | length 11.7
  TopLayer w0.25: v2(8.025,2.775) 8.525,2.275 v2(8.525,-0.175)
  BottomLayer w0.25: U5.16 4.461,3.864 5.55,2.775 v2(8.025,2.775) ; v2(8.525,-0.175) 8.545,-0.195 U1.12
SPI_DOUT: U1.11 U5.15 | length 9.5
  TopLayer w0.25: v2(6.025,3.525) 7.225,2.325 v2(7.225,-0.075)
  BottomLayer w0.25: U5.15 5.111,4.439 v2(6.025,3.525) ; v2(7.225,-0.075) 7.225,-2.129 U1.11
SPI_SCLK: U1.13 U5.1 | length 19.9
  BottomLayer w0.3: U5.1 4.439,9.514 3.05,8.125 3.05,3.4 5.025,1.425 8.6,1.425 9.815,0.21 U1.13
SSEL1: R12.2 U1.3 U2.11 | length 42.7
  BottomLayer w0.25: U1.3 11.085,-9.64 12.075,-8.65 19.375,-8.65 21.8,-6.225 39.65,-6.225 40,-5.875 ; R12.2 40,-5.875 ; U2.11 43.9,-1.975 40,-5.875
TP+: J2.1 R3.1 R21.2 U5.11 | length 58
  BottomLayer w0.4: U5.11 7.711,9.286 9.35,10.925 19.15,10.925 22.675,14.45 22.675,23.075 25.325,25.725
  BottomLayer w0.6: R3.1 17.302,21.527 20.825,25.05 24.55,25.05 25.325,25.825 25.325,26.839 R21.2 ; R21.2@25.481,26.806 J2.1
TX485: U2.9
VCC3.3: C1.1 C3.2 C10.1 C11.1 C12.1 C13.1 C43.1 C44.1 CA1.1 CA13.1 CA14.1 FB7.2 J9.1 J9.2 P3.1 P3V3.1 R1.1 R2.1 R4.1 R5.1 R6.1 R7.2 R9.1 R10.1 R12.1 R13.1 R14.1 R17.1 R22.1 U1.1 U2.1 U2.6 U2.19 U2.27 U12.2 U12.8 | length 217.4
  TopLayer w0.5: v1(75.351,17.976) 76.324,17.976
  TopLayer w0.6: 46.425,2.55 46.45,2.575 v1(46.45,3.425) ; 49.7,3.25 49.824,3.126 v1(53.025,3.126)
  TopLayer w0.8: v1(66.837,-8.838) v1@66.95,-8.725 ; v1(75.301,20.501) 76.35,19.452
  TopLayer w1: v1(33.226,0.576) 33.286,0.636 v1(39.389,0.636) 40.811,0.636 42.076,1.901 ; P3V3.1 49.7,3.25 49,2.55 46.425,2.55 42.725,2.55 42.076,1.901 ; v1(58.499,-0.426) 57.574,-0.426 56.8,-1.2 56.8,-5.85 55.75,-6.9 ; v1@66.95,-8.725 66.95,-6.175 ; J9.2 J9.1 77.475,25.625 76.35,24.5 76.35,19.452 76.35,9.375 73.1,6.125 69.875,6.125 66.95,3.2 66.95,-6.175 ; 42.076,1.901 42.076,-7.849 v1(43.026,-8.799) 44.825,-7 49.686,-7 49.786,-6.9 55.75,-6.9 ; 55.75,-6.9 66.225,-6.9 66.95,-6.175
  BottomLayer w0.3: C11.1 48,-4.343 U2.6 ; C13.1 45.779,4.151 46.5,3.43 U2.19 ; FB7.2 47.586,11.939 47.025,12.5 47.025,13.525 46.663,13.887 R7.2 45.849,14.999 46.525,15.675 48.825,15.675 51.724,18.574 v1(51.724,18.799) ; U2.1 50.5,-3.85 v1(53.638,-6.988) C10.1 ; U2.27 50.5,2.85 50.776,3.126 v1(53.025,3.126) C12.1
  BottomLayer w0.5: U12.8 33.035,2.191 CA14.1 ; CA13.1@39.394,2.231 40.655,3.491 U12.2 ; R14.1 44.013,-8.33 C11.1 ; v1(51.724,18.799) R2.1 ; R13.1 v1(58.499,-0.426) ; R1.1 v1(66.837,-8.838) ; v1(75.301,20.501) R5.1 R4.1 ; v1(75.351,17.976) R17.1 ; R22.1 v1(76.303,11.378)
  BottomLayer w0.6: U1.1 14.8,-11.45 15.512,-10.738 C1.1 C3.2 20.323,-9.214 CA1.1 26.664,-9.214 P3.1 29.7,-11.025 30.25,-10.475 v1(33.275,-10.475) R9.1 R6.1 R10.1 R12.1 40.8,-10.475 42.476,-8.799 v1(43.026,-8.799) R14.1
  BottomLayer w0.8: 15.512,-10.738 C1.1 ; v1(33.226,0.576) CA14.1 ; v1(39.389,0.636) CA13.1
  BottomLayer w1: CA14.1@32.975,1.749 CA14.1 ; FB7.2 49.7,11.364 P3V3.1
VCC_COM: C45.1 C46.2 CA15.1 CA16.1 R41.1 U12.12 U12.19 | length 33
  BottomLayer w0.5: CA15.1 25.301,16.013 C45.1 28.012,15.575 31.4,15.575 ; U12.12 31.765,15.94 31.4,15.575 ; R41.1 40.655,19.982 U12.19 40.655,15.97 ; CA16.1 47.086,17.963 C46.2 44.626,17.001 42.95,15.325 41.3,15.325 40.655,15.97 ; 31.4,15.575 33.45,13.525 39.7,13.525 40.655,14.48 40.655,15.97
  other v1: 28.875,15.575 45.65,17.95 40.625,18.925
VDD_ISO: C2.1 C6.1 C14.1 C25.1 CA2.1 FB1.1 R23.2 U1.16 U5.13 U7.3 U15.1 U15.14 | length 70
  TopLayer w0.8: v1(4.862,25.612) 3.6,24.35 3.6,19.275 ; v1(10.3,20.525) 4.85,20.525 3.6,19.275 ; v1(16.175,1.7) 13.35,4.525 7.225,4.525 3.6,8.15 3.6,19.275
  BottomLayer w0.3: U5.13 6.411,5.314 7.25,4.475 11.011,4.475 C14.1
  BottomLayer w0.4: v1(4.862,25.612) C25.1 ; C25.1@6.813,25.6 U15.1 ; v1(10.3,20.525) 10.6,20.525 10.85,20.275 U15.14 ; CA2.1@14.836,1.8 CA2.1@14.836,2.214
  BottomLayer w0.5: CA2.1 14.836,0.386 13.625,-0.825 U1.16 14.034,-2.588 R23.2 ; CA2.1@14.836,1.8 14.9,1.736 CA2.1@14.9,1.712 ; C6.1 C6.1@18.915,1.726 ; v1(19.25,3.075) 19.25,4.862 FB1.1 ; C6.1@19.274,1.945 v1@19.274,3.075 ; U7.3 U7.3@20.768,1.726
  BottomLayer w0.8: CA2.1@14.9,1.712 C2.1 C6.1 ; C6.1@18.915,1.726 U7.3@20.768,1.726
  other v1: 17.975,1.75 10.45,4.475
VREF: C33.1 C35.1 FB2.2 U5.9 U15.9 | length 28.1
  TopLayer w0.5: v1(14.5,16.45) 14.5,10.475 v1(15.575,9.4)
  BottomLayer w0.3: U5.9 9.011,7.561 9.625,8.175 C35.1@11.249,8.175
  BottomLayer w0.35: C33.1 13.526,17.526 14.1,18.1 U15.9
  BottomLayer w0.5: C35.1 12.513,8.163 13.75,9.4 20.425,9.4 21.024,8.801 FB2.2 ; C33.1 14.462,16.412 v1(14.5,16.45)
pads on no net: J9.11 J9.17 J9.19 P3.4 P4.1 P4.2 P4.3 P4.4 U1.7 U2.7 U2.15 U2.16 U2.20 U2.32 U2.33 U2.34 U5.2 U5.4 U6.7 U6.9 U15.2 U15.3 U15.7

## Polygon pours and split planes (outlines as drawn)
GND_ISO on TopLayer "BottomLayer-No Net" (hatched 90Degree grid 0.3 track 0.3, remove dead copper, pour order 10): -11.05,-4.875 18.7,-4.875 24.025,0.45 24.025,23.925 28.275,28.175 29.825,29.725 29.825,37.6 -12.075,37.6 -12.2,37.475 -12.2,-4.825 -12.15,-4.875
GND_COM on TopLayer "BottomLayer-No Net" (hatched 90Degree grid 0.3 track 0.3, remove dead copper, pour order 8): 28.325,21.125 46.5,21.125 46.55,21.175 46.55,17.25 42,12.7 28.475,12.7 28.3,12.875
VCC3.3 on TopLayer "BottomLayer-No Net" (hatched 90Degree grid 0.3 track 0.3, remove dead copper, pour order 7): 49.025,10.475 50.675,10.475 51.9,9.25 52.4,8.75 52.4,2.05 49.125,2.05 49.05,1.975
GND on TopLayer "BottomLayer-No Net" (hatched 90Degree grid 0.3 track 0.3, remove dead copper, pour order 15): -2.3,-6.275 19.05,-6.275 24.625,-0.7 25.025,-0.3 25.025,9.95 25.025,11.375 43.375,11.375 46.35,14.35 51.6,19.6 51.6,37.55 85.45,37.55 85.45,-13.575 85.25,-13.775 -2.025,-13.775 -2.275,-13.525 -2.275,-6.325 -2.3,-6.3
GND_ISO on BottomLayer "BottomLayer-No Net" (hatched 90Degree grid 0.3 track 0.3, remove dead copper, pour order 12): -11.975,-4.95 18.5,-4.95 23.975,0.525 23.975,21.45 24,21.475 -11.75,21.475 -11.975,21.25
GND on BottomLayer "BottomLayer-No Net" (hatched 90Degree grid 0.3 track 0.3, remove dead copper, pour order 17): -2.425,-6.3 18.95,-6.3 24.8,-0.45 25.1,-0.15 25.1,8.6 25.1,11.5 43.55,11.5 50.825,18.775 51.724,19.674 51.724,22.351 51.724,21.901 51.75,21.875 85.3,21.875 85.375,21.95 85.375,-13.7 85.25,-13.825 -2.425,-13.825

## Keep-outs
KeepOutLayer:
  lines w0.3: 16.125,28.675 16.125,44.6 ; 16.15,28.675 ccw(c17.868,29.213) 19.586,28.675 ; 19.572,28.625 19.572,44.325 ; 24,28.7 24,45.925 ; 24.025,28.7 ccw(c24.638,28.892) 25.25,28.7 25.25,45.85
  lines w0.5: -7.235,-4.177 cw(c-7.38,-9.155) -2.402,-9.01 ; -7.235,-4.175 -12.1,-4.175 -12.1,33.825 -7.235,33.825 ; -7.235,33.827 ccw(c-7.38,38.805) -2.402,38.66 ; -2.425,-9.01 -2.425,-13.825 75.6,-13.825 75.6,-9.355 ; -2.4,38.66 -2.4,43.65 75.575,43.65 75.575,38.966 ; 75.602,-9.21 cw(c80.58,-9.355) 80.435,-4.377 ; 75.603,38.817 ccw(c80.716,38.966) 80.567,33.852 ; 80.58,-4.375 85.375,-4.375 85.375,33.85 80.716,33.85

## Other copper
TopLayer:
  pour cut-out: 4.45,44.25 4.45,31.825 10.25,31.825 10.55,31.525 10.55,23.8 11.375,22.975 14.7,22.975 16.175,24.45 16.175,44.25
BottomLayer:
  pour cut-out: 58.55,17.025 62.15,17.025 62.175,17 62.175,13.2 62.2,13.175 58.525,13.175

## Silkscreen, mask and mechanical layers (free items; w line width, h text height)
TopOverlay:
  lines w0.2: 27.88,-13.5 50.5,-13.5 50.5,26.595 27.88,26.595 27.88,-13.5
  text "GUARD  INP" at 5.45,28.475 h1
  text "- RS485 +   PE" at 35.95,28.375 h1
  text "+24V   GND   PE" at 50.675,28.275 h1
  text "VCM  - Temp +" at 21.4,28.175 h1
  text "SPLora module" at 30.875,11.9 h1
  text "SPMsensor_RS485" at -5.325,7.975 h1.2 r90
  text "JTAG" at 76.825,5.525 h0.8 r270
Mechanical1:
  lines w0.2: 25.326,25.301 43.554,25.301
  lines w0.25: -14.175,30 76.025,30 ; -13.4,33.675 76.8,33.675 ; -13.15,0 87.65,0 ; 0.475,-4.875 0.475,36.625 ; 72.95,-5.025 72.95,45.8
  lines w0.254: -12.925,43.65 87.175,43.65 ; -12.096,-13.814 88.414,-13.814 ; 6.975,26.45 6.975,42.85 ; 85.375,-12.675 85.375,46.95
  lines w0.3: -12.094,-18.55 -12.094,55.4 ; 29.7,-13.175 29.7,29.35 ; 56.2,-30.025 56.2,46.1

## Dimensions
40.797,-12.224 to 46.739,25.301 on Mechanical1
-13.725,15 to -13.125,0 on Mechanical1
-13.175,-13.816 to -14.15,15 on Mechanical1
0.475,-3.2 to 72.95,-3.875 on Mechanical1
-12.096,-13.814 to 85.375,-12.675 on Mechanical1
-12.096,-13.814 to -12.925,43.65 on Mechanical1
6.975,42.325 to 0.475,36.625 on Mechanical1
-12.975,43.675 to -12.7,33.675 on Mechanical1
-13.725,30 to -13.125,15 on Mechanical1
